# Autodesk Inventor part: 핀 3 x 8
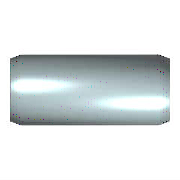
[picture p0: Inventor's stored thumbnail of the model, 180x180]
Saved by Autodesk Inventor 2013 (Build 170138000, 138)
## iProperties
IsCustomPart: 1
Created: 2012-02
Part Number: 핀 3 x 8
Material: 강철, 연강
Description: 평행 핀
Document SubType Name: Modeling
Standard: KS B 1320
Designer: mduedu
Standards Organization: KS
Language: ko-KR
Size Designation: B 3 x  8
Categories: <MemberInstance><Categories><Category DisplayName="조임쇠" InternalName="e4da775c-781d-43d5-af7c-5136215cf5a6" Mnemonic="FSTN"><Category DisplayName="핀" InternalNa
Density: 1 g/cm^3
Author: mduedu
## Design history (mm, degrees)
sketch "스케치"
  geometry: C1 r 1.5 at (0, 0); 1 further point
  constraints: 1 centre point, 1 coincident
  dimensions: "d1" = 3 diameter of C1 (= NND)
extrude "본체" new body sketch "스케치" distance "d2" = 8 (= NLG); taper "d3" = 0 deg
chamfer "스케치2" distance "d8" = 0.5 (= PHH); stored, may be unused: angle "d9" = 15 deg (= FAWI), second distance "d12" = 0.5 (= PHH)
body "Solid1"
chamfer "모따기1" distance "d4" = 0.5 (= PHH); stored, may be unused: angle "d5" = 15 deg (= FAWI), second distance "d11" = 0.5 (= PHH)
other parameters: "NND" = 3 [user parameter; used in 1 equation term], "NLG" = 8 [user parameter; used in 1 equation term], "PHH" = 0.5 [user parameter; used in 4 equation terms], "FAWI" = 15 deg [user parameter; used in 2 equation terms], "d13" = 0, "d15" = 0, "d16" = 0, "KAH" = 0.4 [user parameter]
